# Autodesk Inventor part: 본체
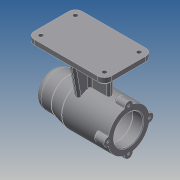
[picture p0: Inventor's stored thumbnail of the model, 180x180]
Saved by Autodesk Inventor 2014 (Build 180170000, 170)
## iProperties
Created: 2019-07
Part Number: 본체
Material: Generic
Document SubType Name: Modeling
Designer: kb542-3
Density: 1 g/cm^3
Appearance: Default
Author: kb542-3
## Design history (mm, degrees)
sketch "스케치1"
  geometry: L1 (0, 0)-(112, 0); L2 (0, 0)-(0, 25); L3 (0, 25)-(25, 25); L4 (25, 25)-(45, 30); L5 (45, 30)-(112, 30); L6 (112, 30)-(112, 0)
  constraints: 12 end point, 2 parallel, 2 perpendicular, 1 horizontal
  dimensions: "d0" = 25 distance of L2.end L3.end; "d1" = 45 distance from line of L4.end L2; "d2" = 112 distance between parallel lines of L6 L2; "d3" = 50 diameter of L3 L1; "d4" = 60 diameter of L5 L1
revolve "회전1" sketch "스케치1" stored, may be unused: angle "d5" = 90 deg
sketch "스케치2"
  geometry: L1 (0, 0)-(-112, 0); L2 (-112, 30)-(-112, -30) reference; L3 (-6, 10.5)-(-6, 0); L4 (-6, 10.5)-(-9, 10.5); L5 (-9, 10.5)-(-9, 16); L6 (-9, 16)-(-13, 16); L7 (-13, 16)-(-13, 17.5); L8 (-13, 17.5)-(-31, 17.5); L9 (-31, 17.5)-(-31, 21); L10 (-31, 21)-(-43, 21); L11 (-43, 21)-(-43, 24); L12 (-43, 24)-(-97, 24); L13 (-97, 24)-(-97, 21); L14 (-97, 21)-(-112, 21)
  constraints: 26 end point, 7 perpendicular, 5 parallel, 2 point on line, 1 midpoint
  dimensions: "d6" = 21 diameter of L4 L1; "d7" = 32 diameter of L6 L1; "d8" = 3 distance of L3.start L4.end; "d9" = 4 distance of L5.end L6.end; "d10" = 18 distance of L7.end L8.end; "d11" = 35 diameter of L8 L1; "d12" = 12 distance of L9.end L10.end; "d13" = 42 diameter of L10 L1; "d14" = 54 distance of L11.end L12.end; "d15" = 48 diameter of L12 L1; "d16" = 15 distance of L13.end L14.end; "d17" = 42 diameter of L14 L1
revolve "회전2" sketch "스케치2" stored, may be unused: angle "d18" = 90 deg
sketch "스케치3"
  geometry: C1 r 21 at (0, 0) reference; A1 r 30 centre (0, 0) between (-5.97, 29.4) and (5.97, 29.4) reference; A2 r 6 centre (0, 30) between (5.97, 29.4) and (-5.97, 29.4)
  constraints: 4 point on circle, 1 centre point, 1 vertical alignment
  dimensions: "d19" = 6 radius of A2; "d20" = 30 distance of A2.centre C1.centre
extrude "돌출1" join sketch "스케치3" distance "d21" = 16; taper "d22" = 0 deg
sketch "스케치4"
  geometry: A1 r 6 centre (0, 0) between (5.97, -0.6) and (-5.97, -0.6) reference; 1 further point
  constraints: 1 coincident
hole "구멍1" sketch "스케치4" at (0, 0) diameter "d23" = 3.242; stored, may be unused: countersink angle "d27" = 90 deg, drill point angle "d29" = 118 deg; dims "d24" = 8, "d25" = 4, "d26" = 2, "d28" = 11
fillet "모깎기1" dims "d30" = 3
fillet "모깎기2" dims "d31" = 1
fillet "모깎기12" dims "d88" = 3
sketch "스케치5"
  geometry: L1 (0, 70)-(-112, 70); L2 (-112, 70)-(-112, 80); L3 (-112, 80)-(0, 80); L4 (0, 80)-(0, 70); L5 (0, 25)-(0, -25) reference; L6 (-112, 36)-(-112, 30.171) reference; 1 further point
  constraints: 8 end point, 2 parallel, 1 horizontal, 1 perpendicular, 1 point on line
  dimensions: "d35" = 10 distance of L3.end L1.start; "d36" = 80 distance from line of L3 point (0, 0); "d37" = 112 distance of L2.end L3.end
extrude "돌출2" join sketch "스케치5" stored distance "d38" = 70; taper "d39" = 0 deg
node "작업 평면1"
fillet "모깎기3" dims "d63" = 10
sketch "스케치8"
  geometry: A1 r 10 centre (0, 60) between (0, 70) and (-10, 60) reference; A2 r 10 centre (0, 10) between (-10, 10) and (0, 0) reference; A3 r 10 centre (92, 10) between (92, 0) and (102, 10) reference; A4 r 10 centre (92, 60) between (102, 60) and (92, 70) reference; 5 further points
  constraints: 4 coincident
hole "구멍2" sketch "스케치8" at (0, 60), (0, 10), (92, 10), (92, 60) diameter "d64" = 6; stored, may be unused: countersink angle "d68" = 90 deg, drill point angle "d70" = 118 deg; dims "d65" = 8, "d66" = 4, "d67" = 2, "d69" = 11
chamfer "모따기1" distance "d71" = 3; stored, may be unused: second distance "d72" = 2, angle "d73" = 45 deg
node "작업 평면2"
sketch "스케치9"
  geometry: L1 (-33.5, -6.771)-(-33.5, -29.226) reference; 2 further points
  constraints: 1 horizontal alignment, 1 other
  dimensions: "d74" = 42 distance from line of L1 point (8.5, 0)
feature "엠보싱1" sketch "스케치9" dims "d0" = 25, "d1" = 45, "d2" = 112, "d3" = 50, "d4" = 60, "d6" = 21, "d7" = 32, "d8" = 3, "d9" = 4, "d10" = 18, "d11" = 35, "d12" = 12, "d13" = 42, "d14" = 54, "d15" = 48, "d16" = 15, "d17" = 42, "d75" = 0.5, "d76" = 0
fillet "모깎기4" dims "d77" = 10
fillet "모깎기5" dims "d78" = 3
chamfer "모따기2" distance "d79" = 1; stored, may be unused: second distance "d80" = 2, angle "d81" = 45 deg
fillet "모깎기13" dims "d89" = 3
fillet "모깎기14" dims "d90" = 0.3
fillet "모깎기15" dims "d91" = 3
fillet "모깎기16" dims "d92" = 3
sketch "스케치10"
  geometry: L1 (-100.026, 30)-(-101, 31.621) reference; L2 (-101, 31.621)-(-112, 31.621) reference; L3 (-112, 31.621)-(-112, 36) reference; L4 (-112, 36)-(-99, 36) reference; L5 (-96, 33)-(-96, 31) reference; L6 (-95, 30)-(-45.369, 30) reference; L7 (-44.642, 29.91)-(-25.358, 25.09) reference; L8 (-24.631, 25)-(-10, 25) reference; L9 (0, 15)-(0, -15) reference; L10 (-10, -25)-(-24.631, -25) reference; L11 (-25.358, -25.09)-(-44.642, -29.91) reference; L12 (-45.369, -30)-(-95, -30) reference; L13 (-96, -31)-(-96, -33) reference; L14 (-99, -36)-(-112, -36) reference; L15 (-112, -36)-(-112, -31.621) reference; L16 (-112, -31.621)-(-101, -31.621) reference; L17 (-101, -31.621)-(-100.026, -30) reference; L18 (-100.026, -30)-(-101, -28.379) reference; L19 (-101, -28.379)-(-112, -28.379) reference; L20 (-112, -28.379)-(-112, -22) reference; L21 (-112, -22)-(-111, -21) reference; L22 (-111, -21)-(-97, -21) reference; L23 (-94, -24)-(-46, -24) reference; L24 (-43, -21)-(-31.3, -21) reference; L25 (-31, -20.7)-(-31, -17.5) reference; L26 (-31, -17.5)-(-13.3, -17.5) reference; L27 (-13, -17.2)-(-13, -16) reference; L28 (-13, -16)-(-9.3, -16) reference; L29 (-9, -15.7)-(-9, -10.5) reference; L30 (-6, -7.5)-(-6, 7.5) reference; L31 (-9, 10.5)-(-9, 15.7) reference; L32 (-9.3, 16)-(-13, 16) reference; L33 (-13, 16)-(-13, 17.2) reference; L34 (-13.3, 17.5)-(-31, 17.5) reference; L35 (-31, 17.5)-(-31, 20.7) reference; L36 (-31.3, 21)-(-43, 21) reference; L37 (-46, 24)-(-94, 24) reference; L38 (-97, 21)-(-111, 21) reference; L39 (-111, 21)-(-112, 22) reference; L40 (-112, 22)-(-112, 28.379) reference; L41 (-112, 28.379)-(-101, 28.379) reference; L42 (-101, 28.379)-(-100.026, 30) reference; L43 (-109, 70)-(-112, 73) reference; L44 (-112, 73)-(-112, 80) reference; L45 (-112, 80)-(0, 80) reference; L46 (0, 80)-(0, 73) reference; L47 (0, 73)-(-3, 70) reference; L48 (-3, 70)-(-109, 70) reference; L49 (-87, 30)-(-87, 70); L50 (-10, 70)-(-102, 70) reference; L51 (-35.43, 27.607)-(-20, 70); A1 r 3 centre (-99, 33) between (-96, 33) and (-99, 36) reference; A2 r 1 centre (-95, 31) between (-96, 31) and (-95, 30) reference; A3 r 3 centre (-45.369, 27) between (-44.642, 29.91) and (-45.369, 30) reference; A4 r 3 centre (-24.631, 28) between (-25.358, 25.09) and (-24.631, 25) reference; A5 r 10 centre (-10, 15) between (0, 15) and (-10, 25) reference; A6 r 10 centre (-10, -15) between (-10, -25) and (0, -15) reference; A7 r 3 centre (-24.631, -28) between (-24.631, -25) and (-25.358, -25.09) reference; A8 r 3 centre (-45.369, -27) between (-45.369, -30) and (-44.642, -29.91) reference; A9 r 1 centre (-95, -31) between (-95, -30) and (-96, -31) reference; A10 r 3 centre (-99, -33) between (-99, -36) and (-96, -33) reference; A11 r 3 centre (-94, -21) between (-97, -21) and (-94, -24) reference; A12 r 3 centre (-46, -21) between (-46, -24) and (-43, -21) reference; A13 r 0.3 centre (-31.3, -20.7) between (-31.3, -21) and (-31, -20.7) reference; A14 r 0.3 centre (-13.3, -17.2) between (-13.3, -17.5) and (-13, -17.2) reference; A15 r 0.3 centre (-9.3, -15.7) between (-9.3, -16) and (-9, -15.7) reference; A16 r 3 centre (-9, -7.5) between (-9, -10.5) and (-6, -7.5) reference; A17 r 3 centre (-9, 7.5) between (-6, 7.5) and (-9, 10.5) reference; A18 r 0.3 centre (-9.3, 15.7) between (-9, 15.7) and (-9.3, 16) reference; A19 r 0.3 centre (-13.3, 17.2) between (-13, 17.2) and (-13.3, 17.5) reference; A20 r 0.3 centre (-31.3, 20.7) between (-31, 20.7) and (-31.3, 21) reference; A21 r 3 centre (-46, 21) between (-43, 21) and (-46, 24) reference; A22 r 3 centre (-94, 21) between (-94, 24) and (-97, 21) reference; 1 further point
  constraints: 4 end point, 4 point on line, 1 perpendicular
  dimensions: "d93" = 20 horizontal distance of L45.end L51.end; "d94" = 25 distance between parallel lines of L44 L49; "d95" = 110 deg angle of L50 L51
extrude "돌출4" join sketch "스케치10" stored distance "d96" = 8; taper "d97" = 0 deg
node "작업 평면3"
sketch "스케치11"
  geometry: L1 (25, 70)-(-25, 70) reference; L2 (-28, 70)-(-19.654, 22.666); L3 (28, 70)-(19.654, 22.666); L4 (-35, 73)-(-35, 80) reference; L5 (35, 80)-(35, 73) reference; L6 (30.493, -0.648)-(29.993, -0.648) reference; L7 (0, 30)-(-4, 30) reference; L8 (-4, 30)-(-4, 70) reference; L9 (-4, 70)-(-32, 70) reference; L10 (-32, 70)-(-35, 73) reference; L11 (-35, 73)-(-35, 80) reference; L12 (-35, 80)-(35, 80) reference; L13 (35, 80)-(35, 73) reference; L14 (35, 73)-(32, 70) reference; L15 (32, 70)-(4, 70) reference; L16 (4, 70)-(4, 30) reference; L17 (4, 30)-(0, 30) reference; L18 (29.999, -0.254)-(30.499, -0.254) reference; C1 r 24 at (0, 0) reference; A1 r 30 centre (0, 0) between (0, 30) and (19.654, 22.666) reference; A2 r 30 centre (0, 0) between (29.999, -0.254) and (0, 30) reference; A3 r 30 centre (0, 0) between (0, 30) and (29.993, -0.648) reference; A4 r 30.5 centre (0, 0) between (30.493, -0.648) and (30.499, -0.254) reference; 1 further point
  constraints: 4 end point, 2 point on circle, 2 point on line
  dimensions: "d99" = 7 distance from line of L2.start L4; "d100" = 7 distance from line of L3.start L5; "d101" = 100 deg angle of L15 L3; "d102" = 100 deg angle of L2 L9
  node "절단 모서리 투영2"
feature "리브3" dims "d103" = 1, "d104" = 8, "d105" = 0, "d106" = 0, "d107" = 1, "d108" = 1
feature "리브4" dims "d109" = 1, "d110" = 8, "d111" = 0, "d112" = 0, "d113" = 1, "d114" = 1
fillet "모깎기17" dims "d115" = 3
fillet "모깎기18" dims "d116" = 3
fillet "모깎기19" dims "d117" = 3
node "솔리드1"
pattern_circular "원형 패턴1" dims "d33" = 360 deg
node "절단 모서리 투영1"
other parameters: "d46" = 56, "d98" = 56
